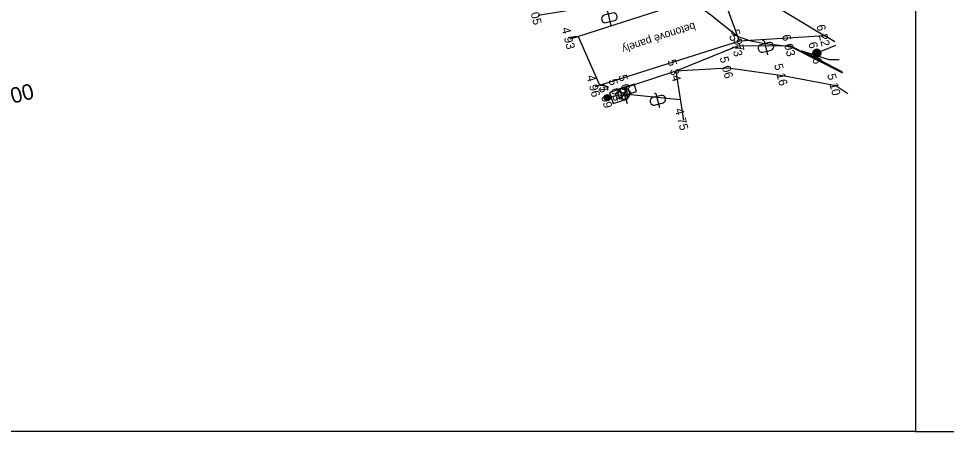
# Model space of a CAD drawing. Extents: x -740053 to -737517, y -1033516 to -1032488.
# Drawn here: x -739046.7 to -738987.3, y -1032655 to -1032628.5 of the extents above; entities that cross this region are included whole.
import ezdxf

# ---------------------------------------------------------------- set-up
doc = ezdxf.new("R2010")
doc.units = 0
for name, color, linetype in [('bod-oznac', 7, 'Continuous'), ('bod-vyska', 7, 'Continuous'), ('bod-vyska100', 7, 'Continuous'), ('Contours', 7, 'Continuous'), ('Contours highlighted', 7, 'Continuous'), ('ctv-sit', 7, 'Continuous'), ('el-zariz', 7, 'Continuous'), ('nazvy-bud-povr', 7, 'Continuous'), ('objekty-na-plynovodu', 7, 'Continuous'), ('ploty', 7, 'Continuous'), ('Predmety bez rozlišeni', 7, 'Continuous'), ('promika-formát', 7, 'Continuous'), ('Rozhrani-ploch', 7, 'Continuous'), ('silnice', 7, 'Continuous'), ('Silnoproud', 7, 'Continuous'), ('Terenni-hrana', 7, 'Continuous'), ('Znacky-kultury', 7, 'Continuous')]:
    doc.layers.add(name, color=color, linetype=linetype)

# ---------------------------------------------------------------- blocks, each defined once
blk = doc.blocks.new('_U')
for points in [[(-4999.05, -6988.84), (-4999.04, -6988.91), (-4999.04, -6988.77), (-4999.04, -6988.77)], [(-4999.04, -6988.77), (-4999.03, -6988.98), (-4999.03, -6988.7), (-4999.03, -6988.7)], [(-4999.03, -6988.98), (-4999.04, -6988.77), (-4999.04, -6988.91), (-4999.04, -6988.91)], [(-4999.03, -6988.7), (-4999, -6989.04), (-4999, -6988.63), (-4999, -6988.63)], [(-4999, -6989.04), (-4999.03, -6988.7), (-4999.03, -6988.98), (-4999.03, -6988.98)], [(-4999, -6988.63), (-4998.97, -6989.11), (-4998.97, -6988.57), (-4998.97, -6988.57)], [(-4998.97, -6989.11), (-4999, -6988.63), (-4999, -6989.04), (-4999, -6989.04)], [(-4998.97, -6988.57), (-4998.93, -6989.16), (-4998.93, -6988.51), (-4998.93, -6988.51)], [(-4998.93, -6989.16), (-4998.97, -6988.57), (-4998.97, -6989.11), (-4998.97, -6989.11)], [(-4998.93, -6988.51), (-4998.88, -6989.21), (-4998.88, -6988.46), (-4998.88, -6988.46)], [(-4998.88, -6989.21), (-4998.93, -6988.51), (-4998.93, -6989.16), (-4998.93, -6989.16)], [(-4998.88, -6988.46), (-4998.82, -6989.26), (-4998.82, -6988.42), (-4998.82, -6988.42)], [(-4998.82, -6989.26), (-4998.88, -6988.46), (-4998.88, -6989.21), (-4998.88, -6989.21)], [(-4998.82, -6988.42), (-4998.76, -6989.29), (-4998.76, -6988.38), (-4998.76, -6988.38)], [(-4998.76, -6989.29), (-4998.82, -6988.42), (-4998.82, -6989.26), (-4998.82, -6989.26)], [(-4998.76, -6988.38), (-4998.69, -6989.32), (-4998.69, -6988.36), (-4998.69, -6988.36)], [(-4998.69, -6989.32), (-4998.76, -6988.38), (-4998.76, -6989.29), (-4998.76, -6989.29)], [(-4998.69, -6988.36), (-4998.62, -6989.33), (-4998.62, -6988.34), (-4998.62, -6988.34)], [(-4998.62, -6989.33), (-4998.69, -6988.36), (-4998.69, -6989.32), (-4998.69, -6989.32)], [(-4998.62, -6988.34), (-4998.55, -6989.34), (-4998.55, -6988.34), (-4998.55, -6988.34)], [(-4998.55, -6989.34), (-4998.62, -6988.34), (-4998.62, -6989.33), (-4998.62, -6989.33)], [(-4998.55, -6988.34), (-4998.48, -6989.33), (-4998.48, -6988.34), (-4998.48, -6988.34)], [(-4998.48, -6989.33), (-4998.55, -6988.34), (-4998.55, -6989.34), (-4998.55, -6989.34)], [(-4998.48, -6988.34), (-4998.41, -6989.32), (-4998.41, -6988.36), (-4998.41, -6988.36)], [(-4998.41, -6989.32), (-4998.48, -6988.34), (-4998.48, -6989.33), (-4998.48, -6989.33)], [(-4998.41, -6988.36), (-4998.34, -6989.29), (-4998.34, -6988.38), (-4998.34, -6988.38)], [(-4998.34, -6989.29), (-4998.41, -6988.36), (-4998.41, -6989.32), (-4998.41, -6989.32)], [(-4998.34, -6988.38), (-4998.28, -6989.26), (-4998.28, -6988.42), (-4998.28, -6988.42)], [(-4998.28, -6989.26), (-4998.34, -6988.38), (-4998.34, -6989.29), (-4998.34, -6989.29)], [(-4998.28, -6988.42), (-4998.22, -6989.21), (-4998.22, -6988.46), (-4998.22, -6988.46)], [(-4998.22, -6989.21), (-4998.28, -6988.42), (-4998.28, -6989.26), (-4998.28, -6989.26)], [(-4998.22, -6988.46), (-4998.17, -6989.16), (-4998.17, -6988.51), (-4998.17, -6988.51)], [(-4998.17, -6989.16), (-4998.22, -6988.46), (-4998.22, -6989.21), (-4998.22, -6989.21)], [(-4998.17, -6988.51), (-4998.13, -6989.11), (-4998.13, -6988.57), (-4998.13, -6988.57)], [(-4998.13, -6989.11), (-4998.17, -6988.51), (-4998.17, -6989.16), (-4998.17, -6989.16)], [(-4998.13, -6988.57), (-4998.1, -6989.04), (-4998.1, -6988.63), (-4998.1, -6988.63)], [(-4998.1, -6989.04), (-4998.13, -6988.57), (-4998.13, -6989.11), (-4998.13, -6989.11)], [(-4998.1, -6988.63), (-4998.07, -6988.98), (-4998.07, -6988.7), (-4998.07, -6988.7)], [(-4998.07, -6988.98), (-4998.1, -6988.63), (-4998.1, -6989.04), (-4998.1, -6989.04)], [(-4998.07, -6988.7), (-4998.06, -6988.91), (-4998.06, -6988.77), (-4998.06, -6988.77)], [(-4998.06, -6988.91), (-4998.07, -6988.7), (-4998.07, -6988.98), (-4998.07, -6988.98)], [(-4998.05, -6988.84), (-4998.06, -6988.77), (-4998.06, -6988.91), (-4998.06, -6988.91)]]:
    blk.add_lwpolyline(points, close=True)
blk = doc.blocks.new('el_sloup')
blk.add_circle((0, 0), 0.5)
blk.add_blockref('_U', (4998.55, 6988.84))
blk = doc.blocks.new('el_rozd')
for p, q in [((-1, 1), (-1, 0)), ((1, 1), (-1, 1)), ((-1, 0), (1, 0)), ((1, 0), (1, 1))]:
    blk.add_line(p, q)
blk = doc.blocks.new('po_sasou')
for p, q in [((-1.05, 0.76), (-1.05, -0.73)), ((0.95, 0.76), (-1.05, 0.76)), ((0.95, -0.73), (0.95, 0.76)), ((-1.05, -0.73), (0.95, -0.73))]:
    blk.add_line(p, q)
blk.add_text('U', height=1.09).set_placement((-0.58, -0.53))
blk = doc.blocks.new('el_lamst')
for p, q in [((-0.53, 1.66), (0.53, 2.72)), ((-0.53, 2.72), (0.53, 1.66)), ((0, 1.44), (0, 0.4))]:
    blk.add_line(p, q)
for centre, radius in [((0, 2.19), 0.75), ((0, 0), 0.4), ((0, 0), 0.351), ((0, 0), 0.305), ((0, 0), 0.305), ((0, 0), 0.26), ((0, 0), 0.206), ((0, 0), 0.161), ((0, 0), 0.115), ((0, 0), 0.0619)]:
    blk.add_circle(centre, radius)
blk = doc.blocks.new('p_neplod')
for p, q in [((-0.82, 0), (-0.99, -0.18)), ((1, 0), (-0.82, 0)), ((-0.49, 0.56), (-0.49, -0.55)), ((0.05, 1.01), (-0.04, 1.01)), ((0.5, -0.55), (0.5, 0.56)), ((-0.04, -1), (0.05, -1))]:
    blk.add_line(p, q)
for centre, start, end in [((-0.04, 0.56), 90, 180), ((0.05, 0.56), 0, 90), ((-0.04, -0.55), 180, 270), ((0.05, -0.55), 270, 0)]:
    blk.add_arc(centre, 0.45, start, end)
blk = doc.blocks.new('POINT_DISPLAY')
blk.add_line((0, 0), (0, 0))

msp = doc.modelspace()

# ---------------------------------------------------------------- linework, layer by layer
at = {"layer": 'Contours'}
for points in [[(-739013.426, -1032628.333), (-739006.85, -1032627.241), (-739003.603, -1032627.363), (-739003.577, -1032627.422), (-739002.29, -1032628.383), (-739000.652, -1032629.669), (-739000.453, -1032629.769), (-738999.882, -1032629.944), (-738998.907, -1032630.135), (-738997.613, -1032630.29), (-738997.293, -1032630.353), (-738997.182, -1032630.369), (-738993.934, -1032632.025)], [(-738993.952, -1032631.954), (-738996.544, -1032630.606), (-738994.808, -1032631.177), (-738994.149, -1032631.17)]]:
    msp.add_lwpolyline(points, dxfattribs=at)
at = {"layer": 'Contours highlighted'}
for points in [[(-739011.509, -1032629.766), (-739011.079, -1032629.694), (-739010.867, -1032629.702), (-739009.531, -1032632.715), (-739009.404, -1032632.81), (-739009.225, -1032632.82), (-739008.96, -1032632.913), (-739008.976, -1032633.057), (-739009.532, -1032633.14)], [(-739007.706, -1032633.998), (-739007.925, -1032633.358), (-739004.323, -1032633.722)]]:
    msp.add_lwpolyline(points, dxfattribs=at)
at = {"layer": 'ploty'}
for p, q in [((-739001.256, -1032631.722), (-739004.6, -1032631.914)), ((-739004.6, -1032631.914), (-739004.12, -1032635.052)), ((-738997.758, -1032632.223), (-739001.256, -1032631.722)), ((-738994.361, -1032632.853), (-738997.758, -1032632.223)), ((-738993.596, -1032633.368), (-738994.361, -1032632.853))]:
    msp.add_line(p, q, dxfattribs=at)
at = {"layer": 'Predmety bez rozlišeni'}
msp.add_line((-738989.249, -1032654.978), (-739094.249, -1032654.978), dxfattribs=at)
at = {"layer": 'promika-formát'}
msp.add_lwpolyline([(-738989.249, -1032654.978), (-738884.249, -1032654.978), (-738884.249, -1032506.478), (-738989.249, -1032506.478)], close=True, dxfattribs=at)
at = {"layer": 'Rozhrani-ploch'}
msp.add_line((-739000.538, -1032629.984), (-739001.708, -1032626.731), dxfattribs=at)
at = {"layer": 'silnice'}
for p, q in [((-739003.458, -1032627.316), (-739011.375, -1032629.866)), ((-738999.369, -1032627.05), (-738995.065, -1032629.648)), ((-738995.065, -1032629.648), (-739000.538, -1032629.984)), ((-738994.432, -1032630.046), (-738995.065, -1032629.648)), ((-739000.538, -1032629.984), (-739009.769, -1032632.926))]:
    msp.add_line(p, q, dxfattribs=at)
at = {"layer": 'Silnoproud'}
msp.add_line((-738994.376, -1032630.268), (-738995.577, -1032630.766), dxfattribs=at)
at = {"layer": 'Terenni-hrana'}
for p, q in [((-739000.65, -1032630.321), (-739004.6, -1032631.914)), ((-738997.276, -1032630.287), (-739000.65, -1032630.321)), ((-738993.94, -1032631.999), (-738997.276, -1032630.287)), ((-739004.6, -1032631.914), (-739008.382, -1032633.155))]:
    msp.add_line(p, q, dxfattribs=at)

# ---------------------------------------------------------------- block references
at = {"layer": 'bod-oznac', "rotation": -75.86979040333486}
for p in [(-739011.375, -1032629.866), (-738995.065, -1032629.648), (-739000.65, -1032630.321), (-739000.538, -1032629.984), (-738997.276, -1032630.287), (-738995.577, -1032630.766), (-739004.6, -1032631.914), (-739001.256, -1032631.722), (-738997.758, -1032632.223), (-738994.361, -1032632.853), (-739009.769, -1032632.926), (-739008.382, -1032633.155), (-739007.747, -1032632.892), (-739008.997, -1032633.619), (-739004.12, -1032635.052)]:
    msp.add_blockref('POINT_DISPLAY', p, dxfattribs=at)
at = {"layer": 'el-zariz', "yscale": 0.4999999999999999}
for name, p, xscale, rotation in [('el_sloup', (-738995.577, -1032630.766), 0.49999999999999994, -75.86979040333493), ('el_rozd', (-739007.747, -1032632.892), 0.5, -162.40349914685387), ('el_lamst', (-739008.997, -1032633.619), 0.49999999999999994, -75.86979040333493)]:
    msp.add_blockref(name, p, dxfattribs=dict(at, xscale=xscale, rotation=rotation))
at = {"layer": 'objekty-na-plynovodu', "xscale": 0.49999999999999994, "yscale": 0.5, "rotation": -162.8911977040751}
msp.add_blockref('po_sasou', (-739008.285, -1032633.485), dxfattribs=at)
at = {"layer": 'Znacky-kultury', "xscale": 0.49999999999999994, "yscale": 0.5, "rotation": -75.86979040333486}
for p in [(-739008.867, -1032628.499), (-738998.837, -1032630.391), (-739005.759, -1032633.773)]:
    msp.add_blockref('p_neplod', p, dxfattribs=at)

# ---------------------------------------------------------------- texts
at = {"layer": 'bod-vyska'}
for s, p in [('6 05', (-739014.064, -1032627.611)), ('4 93', (-739011.927, -1032629.178)), ('5 97', (-739001.087, -1032629.308)), ('6 22', (-738995.607, -1032628.997)), ('5 73', (-739001.198, -1032629.646)), ('6 03', (-738997.818, -1032629.636)), ('6 06', (-738996.119, -1032630.116)), ('5 06', (-739001.804, -1032631.046)), ('5 34', (-739005.148, -1032631.238)), ('5 16', (-738998.316, -1032631.509)), ('4 96', (-739010.321, -1032632.238)), ('5 06', (-739008.295, -1032632.216)), ('5 10', (-738994.919, -1032632.139)), ('5 09', (-739009.545, -1032632.943)), ('5 03', (-739008.93, -1032632.479)), ('4 75', (-739004.671, -1032634.363))]:
    msp.add_text(s, height=0.55, rotation=284.13021, dxfattribs=at).set_placement(p)
at = {"layer": 'bod-vyska100'}
for s, p in [('284 93', (-739011.449, -1032629.711)), ('285 97', (-739000.612, -1032629.83)), ('286 22', (-738995.138, -1032629.494)), ('285 73', (-739000.723, -1032630.167)), ('286 03', (-738997.349, -1032630.133)), ('286 06', (-738995.65, -1032630.613)), ('285 06', (-739001.329, -1032631.568)), ('285 34', (-739004.673, -1032631.76)), ('285 16', (-738997.832, -1032632.066)), ('284 96', (-739009.843, -1032632.772)), ('285 06', (-739007.82, -1032632.738)), ('285 10', (-738994.435, -1032632.695)), ('285 09', (-739009.07, -1032633.465)), ('285 03', (-739008.455, -1032633.001)), ('284 75', (-739004.193, -1032634.897))]:
    msp.add_text(s, height=0.05, rotation=284.13021, dxfattribs=at).set_placement(p)
at = {"layer": 'ctv-sit'}
msp.add_text('738800', height=1, rotation=14.13021, dxfattribs=at).set_placement((-739049.975, -1032634.733))
at = {"layer": 'nazvy-bud-povr'}
msp.add_text('betonové panely', height=0.5, rotation=198.1366, dxfattribs=at).set_placement((-739003.439, -1032628.781))

doc.saveas('drawing.dxf')
